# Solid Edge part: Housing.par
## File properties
Title: Housing
Author: Dan
Comments: BL 41051 High Duty R75-00
Template: Normal.par
Last saved by: Dan
Revision: 127
Application: Solid Edge
Density: 0 kg/mm^3
Accuracy: 0.99
Document Number: P52-001
Project Name: Piston Pump P52
Material: cast iron
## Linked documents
Piston Housing Core.par
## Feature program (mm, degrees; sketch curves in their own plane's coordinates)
sketch for "unnamed Protrusion 1" plane through (0, 0, 0) normal (1, 0, 0) x-axis (0, 1, 0)
  circle centre (0, 0) radius 47
extrude "unnamed Protrusion 1" add finite 43 along +normal
sketch for "ExtrudedProtrusion_2" plane through (0, 0, 0) normal (1, 0, 0) x-axis (0, 1, 0)
  line (-53.9527, 38.8498) -> (-50.75, 0)
  line (-50.75, 0) -> (-53.9527, -38.8498)
  arc centre (-40, -40) radius 14 from (-40.4886, -53.9915) to (-53.9527, -38.8498) cw
  line (-40.4886, -53.9915) -> (0, -55.4054)
  line (40.4886, -53.9915) -> (0, -55.4054)
  arc centre (40, -40) radius 14 from (53.9527, -38.8498) to (40.4886, -53.9915) cw
  line (50.75, 0) -> (53.9527, -38.8498)
  line (53.9527, 38.8498) -> (50.75, 0)
  arc centre (40, 40) radius 14 from (40.4886, 53.9915) to (53.9527, 38.8498) cw
  line (40.4886, 53.9915) -> (0, 55.4054)
  line (-40.4886, 53.9915) -> (0, 55.4054)
  arc centre (-40, 40) radius 14 from (-53.9527, 38.8498) to (-40.4886, 53.9915) cw
extrude "ExtrudedProtrusion_2" add finite 16.41 along -normal
draft "Draft_10"  Angles21 = 1.5 deg
fillet "Round_15" radius 2
sketch for "ExtrudedProtrusion_3" plane through (-13, 0, 0) normal (1, 0, 0) x-axis (0, 1, 0)
extrude "ExtrudedProtrusion_3" add finite 72 along -normal  Plane_Distance = 13 mm; Treatment1_DraftAngle = 2 deg
sketch for "unnamed RevolvedCutout 1" plane through (0, 0, 0) normal (0, -1, 0) x-axis (1, 0, 0)
  line (-85, 25.5) -> (-82, 25.5)
  line (-82, 25.5) -> (-57.1938, 50.3062)
  arc centre (-51.5369, 44.6494) radius 8 from (-51.8161, 52.6445) to (-57.1938, 50.3062) ccw
  line (-51.8161, 52.6445) -> (-51.8161, 57.098)
revolve "unnamed RevolvedCutout 1" cut full turn 360 deg
fillet "Round_1" radius 2
sketch for "unnamed RevolvedProtrusion 1" plane through (0, 0, 0) normal (0, 0, 1) x-axis (1, 0, 0)
  line (43, 21) -> (43.8787, 21)
  line (43.8787, 21) -> (46, 18.8787)
  line (46, 18.8787) -> (46, 0)
revolve "unnamed RevolvedProtrusion 1" add finite 360 deg about sketch line (46, 0) -> (38.3532, 0)
sketch for "Hole_24" plane through (46, 0, 0) normal (1, 0, 0) x-axis (0, 1, 0)
hole "Hole_24" diameter 17.5 finite  VBottomAngle = 118 deg
sketch for "Dia_32" plane through (46, 0, 0) normal (1, 0, 0) x-axis (0, 0, -1)
hole "Dia_32" finite  Center_Bore_CounterSinkAngle = 90 deg
sketch for "Hole_2" plane through (43, 0, 0) normal (1, 0, 0) x-axis (0, 0, -1)
hole "Hole_2" finite  CounterBoreDepth = 68 mm; CounterSinkAngle = 118 deg; ThreadDepth = 86 mm
sketch for "unnamed Hole 1" plane through (43, 0, 0) normal (1, 0, 0) x-axis (0, 0, -1)
  hole centre (13.0112, 31.4119) bore radius 8.25
hole "unnamed Hole 1" finite
sketch for "unnamed Hole 2" plane through (43, 0, 0) normal (1, 0, 0) x-axis (0, 0, -1)
  hole centre (13.0112, -31.4119) bore radius 8.25
hole "unnamed Hole 2" finite
sketch for "unnamed Hole 3" plane through (43, 0, 0) normal (1, 0, 0) x-axis (0, 0, -1)
  hole centre (-13.0112, -31.4119) bore radius 8.25
hole "unnamed Hole 3" finite
sketch for "unnamed Hole 4" plane through (43, 0, 0) normal (1, 0, 0) x-axis (0, 0, -1)
  hole centre (-31.4119, -13.0112) bore radius 8.25
hole "unnamed Hole 4" finite
sketch for "unnamed Hole 5" plane through (43, 0, 0) normal (1, 0, 0) x-axis (0, 0, -1)
  hole centre (-31.4119, 13.0112) bore radius 8.25
hole "unnamed Hole 5" finite
sketch for "Dia_20" plane through (43, 0, 0) normal (1, 0, 0) x-axis (0, 0, -1)
hole "Dia_20" finite  VBottomAngle = 118 deg
sketch for "unnamed Hole 6" plane through (43, 0, 0) normal (1, 0, 0) x-axis (0, 0, -1)
hole "unnamed Hole 6" finite
pattern "unnamed Pattern 1" of "Hole_2", "unnamed Hole 1", "unnamed Hole 2", "unnamed Hole 3", "unnamed Hole 4", "unnamed Hole 5", "Dia_20", "unnamed Hole 6"
sketch for "unnamed Hole 7" plane through (-16.5, 0, 0) normal (1, 0, 0) x-axis (0, 1, 0)
hole "unnamed Hole 7" through
sketch for "unnamed Hole 8" plane through (-16.5, 0, 0) normal (1, 0, 0) x-axis (0, 1, 0)
  hole centre (40, -40) bore radius 6.25
hole "unnamed Hole 8" through
sketch for "unnamed Hole 9" plane through (-16.5, 0, 0) normal (1, 0, 0) x-axis (0, 1, 0)
  hole centre (40, 40) bore radius 6.25
hole "unnamed Hole 9" through
sketch for "Hole_10" plane through (-16.5, 0, 0) normal (1, 0, 0) x-axis (0, 1, 0)
  hole centre (-40, -40) bore radius 6.25
hole "Hole_10" through  Plane_Distance = 16.5 mm
pattern "unnamed Pattern 2" of "unnamed Hole 7", "unnamed Hole 8", "unnamed Hole 9", "Hole_10"
sketch for "unnamed Hole 10" plane through (-85, 0, 0) normal (-1, 0, 0) x-axis (0, 1, 0)
hole "unnamed Hole 10" finite
sketch for "RevolvedCutout_2" plane through (0, 0, 0) normal (0, 0.382683, 0.92388) x-axis (1, 0, 0)
revolve "RevolvedCutout_2" cut full turn 22.5 deg about sketch line (-26.0001, 0) -> (-60, 0)
fillet "unnamed Round 1"
fillet "Round_16" radius 1
fillet "Round_17" radius 0.6
base feature "unnamed BaseFeature 1"
delete holes assoc c "unnamed DeleteHolesAssocC 1"
sketch for "unnamed RevolvedProtrusion 2" plane through (0, 0, 0) normal (0, -1, 0) x-axis (1, 0, 0)
revolve "unnamed RevolvedProtrusion 2" add full turn 360 deg
sketch for "unnamed RevolvedProtrusion 3" plane through (0, 0, 0) normal (0, -1, 0) x-axis (1, 0, 0)
revolve "unnamed RevolvedProtrusion 3" add full turn 360 deg
sketch for "unnamed Protrusion 2" plane through (0, 0, 0) normal (0, 0, 1) x-axis (1, 0, 0)
extrude "unnamed Protrusion 2" add to key point symmetric
sketch for "unnamed Cutout 1" plane through (0, 0, 0) normal (1, 0, 0) x-axis (0, 1, 0)
  arc centre (-40, 40) radius 10 from (-30.0061, 39.651) to (-39.651, 30.0061) cw
  line (-39.651, 30.0061) -> (-45.0206, 29.8186)
  arc centre (0, 0) radius 54 from (-51.9616, 14.6968) to (-45.0206, 29.8186) cw
  line (-51.9616, 14.6968) -> (-50.75, 0)
  line (-50.75, 0) -> (-51.9616, -14.6968)
  arc centre (0, 0) radius 54 from (-45.0206, -29.8186) to (-51.9616, -14.6968) cw
  line (-39.651, -30.0061) -> (-45.0206, -29.8186)
  arc centre (-40, -40) radius 10 from (-39.651, -30.0061) to (-30.0061, -39.651) cw
  line (-30.0061, -39.651) -> (-29.8186, -45.0206)
  arc centre (0, 0) radius 54 from (29.8186, -45.0206) to (-29.8186, -45.0206) cw
  line (30.0061, -39.651) -> (29.8186, -45.0206)
  arc centre (40, -40) radius 10 from (30.0061, -39.651) to (39.651, -30.0061) cw
  line (39.651, -30.0061) -> (45.0206, -29.8186)
  arc centre (0, 0) radius 54 from (51.9616, -14.6968) to (45.0206, -29.8186) cw
  line (51.9616, -14.6968) -> (50.75, 0)
  line (50.75, 0) -> (51.9616, 14.6968)
  arc centre (0, 0) radius 54 from (45.0206, 29.8186) to (51.9616, 14.6968) cw
  line (39.651, 30.0061) -> (45.0206, 29.8186)
  arc centre (40, 40) radius 10 from (39.651, 30.0061) to (30.0061, 39.651) cw
  line (30.0061, 39.651) -> (29.8186, 45.0206)
  arc centre (0, 0) radius 54 from (-29.8186, 45.0206) to (29.8186, 45.0206) cw
  line (-30.0061, 39.651) -> (-29.8186, 45.0206)
extrude "unnamed Cutout 1" cut through along +normal
sketch for "unnamed RevolvedProtrusion 4" plane through (0, 0, 0) normal (0, 0, 1) x-axis (1, 0, 0)
  line (-106.7128, 13.6651) -> (-107.0412, 23.0698)
  arc centre (-109.04, 23) radius 2 from (-109.04, 25) to (-107.0412, 23.0698) cw
  line (-109.04, 25) -> (-144.04, 25)
  arc centre (-144.04, 23) radius 2 from (-144.04, 25) to (-146.0388, 23.0698) ccw
  line (-146.0388, 23.0698) -> (-146.3206, 15)
  line (-146.3206, 15) -> (-151.3206, 15)
  line (-151.3206, 15) -> (-151.8444, 0)
  line (-60, 12.7) -> (-60, 0)
  line (-105.7134, 12.7) -> (-60, 12.7)
  arc centre (-105.7134, 13.7) radius 1 from (-106.7128, 13.6651) to (-105.7134, 12.7) ccw
  dimension (linear) = 151.3206
  dimension (linear) = 106.7128
revolve "unnamed RevolvedProtrusion 4" add full turn 360 deg about sketch line (-151.8444, 0) -> (-60, 0)
Other named dimensions: "CopyConstruction_1": XScale = 1; YScale = 1; ZScale = 1 | "CoordinateSystem_1": X_Translation = -60 mm
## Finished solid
Body 1: solid body, 17 faces, 16 edges, 1 vertex.
  Faces by surface: torus 6, cylinder 4, plane 4, cone 3
  Edges by curve: circle 16
Body 2: solid body, 195 faces, 404 edges, 200 vertices.
  Faces by surface: cylinder 53, blend 44, torus 35, plane 32, cone 31
  Edges by curve: circle 212, intersection 106, line 82, ellipse 4
Bounding box of the edges (mm; curved faces can reach further): 196.000 x 108.000 x 110.811, from (-150, -54, -55.4054) to (46, 54, 55.4054).
Cylindrical faces by radius (mm): R2 x16, R6.25 x4, R8.25 x8, R10 x8, R12.6046 x1, R14 x4, R15 x1, R15.1455 x1, R16 x1, R21 x1, R25 x1, R25.5 x1, R28 x8, R28.0163 x1, R47 x1
Conical faces (half-angle, radius in mm at the cone's reference point): 2 deg R10 x4, 2 deg R54 x6, 19.9523 deg R17.8199 x1, 19.9523 deg R23.7772 x1, 45 deg R17 x1, 45 deg R21 x1, 45 deg R25.5 x1, 59 deg R8.25 x8, 59 deg R8.75 x1, 59 deg R10 x8, 88 deg R13.5697 x1, 88 deg R23.0698 x1
Toroidal faces (ring radius, tube radius in mm): R0.0916 r44.3294 x1, R0.1079 r44.3294 x1, R8.1877 r2 x4, R10.6 r0.6 x8, R12 r2 x4, R13.6046 r1 x1, R15 r3 x1, R15.0163 r3 x1, R23 r2 x2, R24.7008 r1 x1, R24.7172 r1 x1, R27.5 r2 x1, R44.6494 r8 x6, R46 r1 x1, R55.8123 r2 x8
Planar faces by outward normal: +x 6, -x 10, oblique 20
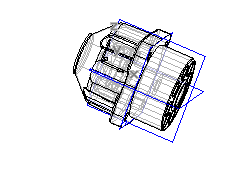
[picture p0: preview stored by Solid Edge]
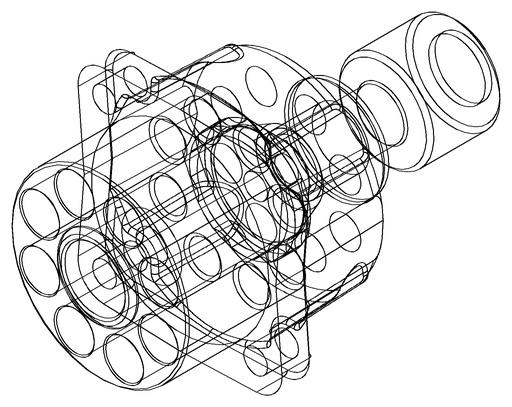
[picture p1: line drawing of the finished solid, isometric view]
